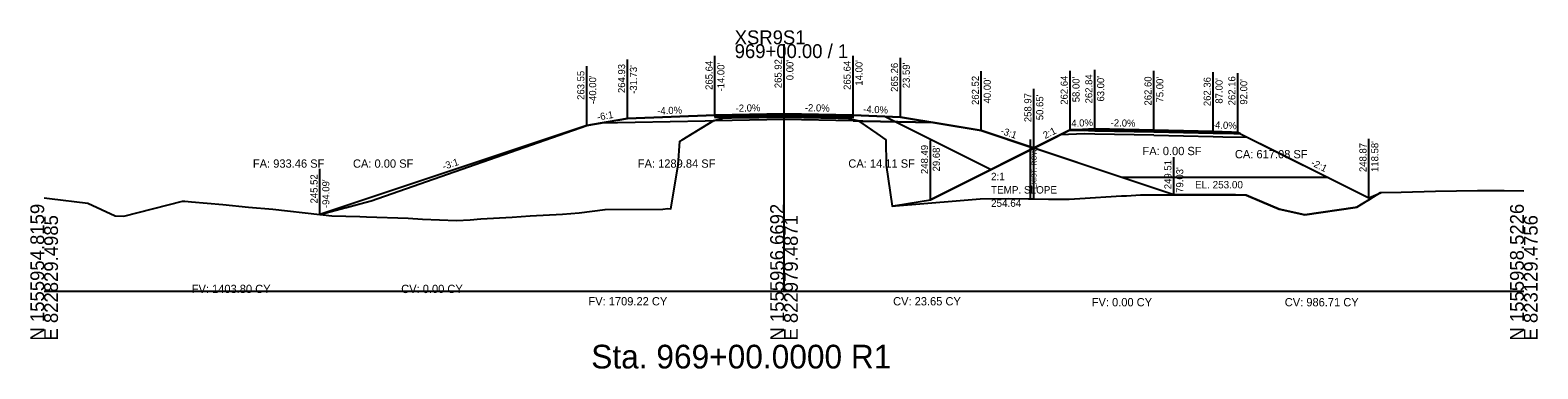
# Model space of a CAD drawing. Extents: x -26 to 823017, y -16 to 1558356.
# Drawn here: x 997.2 to 1302.8, y 9484.3 to 9552.8 of the extents above; entities that cross this region are included whole.
import ezdxf

# ---------------------------------------------------------------- set-up
doc = ezdxf.new("R2010")
doc.units = 0
for name, color, linetype in [('1', 7, 'Continuous'), ('ASPHALT_19MM1', 7, 'Continuous'), ('ASPHALT_9_5MM1', 7, 'Continuous'), ('CONST_DCH', 7, 'Continuous'), ('CONST_LV3', 7, 'Continuous'), ('Draft_XS_Grid', 7, 'Continuous'), ('Draft_XS_Text', 7, 'Continuous'), ('DTM_CORRIDOR', 7, 'Continuous'), ('DTM_P_FINISHED_GRADE2', 7, 'Continuous'), ('DTM_X_GROUND', 7, 'Continuous'), ('SLOPE_STAKES_FILL', 7, 'Continuous'), ('X_PROFILES_1', 7, 'Continuous'), ('X_TRANS_EOP', 7, 'Continuous'), ('XS_CELL', 7, 'Continuous'), ('XS_M_SHAPES_EARTHWORK', 7, 'Continuous'), ('XS_P_DR_GRAVEL', 7, 'Continuous'), ('XS_P_GROUND', 7, 'Continuous'), ('XS_P_NULL_POINT', 7, 'Continuous'), ('XS_P_SHOULDER', 7, 'Continuous'), ('XS_P_SUBGRADE_GRANULAR', 7, 'Continuous'), ('XS_P_SUBGRADE_UNDERCUT', 7, 'Continuous'), ('XS_P_TX_CLEARZONE', 7, 'Continuous'), ('XS_P_TX_FS_BS', 7, 'Continuous'), ('XS_SHEET_EW_TX_AREA', 7, 'Continuous'), ('XS_SHEET_EW_TX_VOLUME', 7, 'Continuous'), ('XS_X_ROW', 7, 'Continuous')]:
    doc.layers.add(name, color=color, linetype=linetype)

msp = doc.modelspace()

# ---------------------------------------------------------------- linework, layer by layer
at = {"layer": '1'}
msp.add_lwpolyline([(1136, 9535.35), (1136, 9535.35), (1150, 9535.63), (1164, 9535.35), (1164, 9535.35), (1164, 9535.51), (1164, 9535.51), (1150, 9535.79), (1136, 9535.51), (1136, 9535.51), (1136, 9535.35)], dxfattribs=at)
at = {"layer": 'ASPHALT_19MM1'}
for points in [[(1136, 9535.14), (1136, 9535.14), (1150, 9535.42), (1164, 9535.14), (1164, 9535.14), (1164, 9535.35), (1164, 9535.35), (1150, 9535.63), (1136, 9535.35), (1136, 9535.35), (1136, 9535.14)], [(1213, 9532.47), (1225, 9532.23), (1237, 9531.99), (1237, 9532.2), (1225, 9532.44), (1213, 9532.68), (1213, 9532.47)]]:
    msp.add_lwpolyline(points, dxfattribs=at)
at = {"layer": 'ASPHALT_9_5MM1'}
msp.add_lwpolyline([(1136, 9535.51), (1136, 9535.51), (1150, 9535.79), (1164, 9535.51), (1164, 9535.51), (1164, 9535.64), (1164, 9535.64), (1150, 9535.92), (1136, 9535.64), (1136, 9535.64), (1136, 9535.51)], dxfattribs=at)
at = {"layer": 'CONST_LV3'}
for points in [[(1150, 9535.92), (1164, 9535.64)], [(1173.59, 9535.26), (1164, 9535.64), (1164, 9535.64)], [(1110, 9533.55), (1112.74, 9534.01), (1112.74, 9534.01)], [(1179.68, 9518.49), (1203.22, 9530.25), (1208, 9532.64), (1209.25, 9532.69), (1213, 9532.84)], [(1190, 9532.52), (1180.23, 9534.15), (1180.23, 9534.15)], [(1200.65, 9528.97), (1200.97, 9529.13), (1203.1, 9530.19), (1203.22, 9530.25), (1208, 9532.64), (1209.25, 9532.69), (1213, 9532.84), (1222.01, 9532.66), (1225, 9532.6), (1234.01, 9532.14), (1237, 9531.99), (1238.25, 9532.03), (1242, 9532.16), (1260.49, 9522.92), (1260.59, 9522.87), (1261.82, 9522.26), (1268.58, 9518.87), (1270.91, 9519.91), (1271.04, 9519.97), (1275.11, 9520.08), (1282.11, 9520.26), (1290.63, 9520.39), (1296.03, 9520.36), (1300, 9520.33)], [(1242, 9532.16), (1268.82, 9518.75)], [(1000, 9518.93), (1001.08, 9518.77), (1008.83, 9517.79), (1014.39, 9515.25), (1016.12, 9515.22), (1028.04, 9518.24), (1028.49, 9518.2), (1029.87, 9518.06), (1036.24, 9517.55), (1041.42, 9517.01), (1046.39, 9516.58), (1055.89, 9515.53), (1055.91, 9515.52), (1055.91, 9515.52), (1055.91, 9515.52)]]:
    msp.add_lwpolyline(points, dxfattribs=at)
at = {"layer": 'DTM_P_FINISHED_GRADE2'}
msp.add_lwpolyline([(1055.91, 9515.52), (1066.32, 9518.3), (1110, 9533.55), (1118.27, 9534.93), (1136, 9535.64), (1150, 9535.92), (1164, 9535.64), (1173.59, 9535.26), (1190, 9532.52), (1200.65, 9528.97)], dxfattribs=at)
at = {"layer": 'DTM_X_GROUND'}
for points in [[(1000, 9518.93), (1001.08, 9518.77), (1008.83, 9517.79), (1014.39, 9515.25), (1016.12, 9515.22), (1028.04, 9518.24), (1028.49, 9518.2), (1029.87, 9518.06), (1036.24, 9517.55), (1041.42, 9517.01), (1046.39, 9516.58), (1055.89, 9515.53), (1055.91, 9515.52), (1055.91, 9515.52), (1055.91, 9515.52), (1056.64, 9515.72), (1059.4, 9516.46), (1061.27, 9516.96), (1065.77, 9518.16), (1066.32, 9518.3), (1110, 9533.55), (1110, 9533.55), (1118.27, 9534.93), (1118.27, 9534.93), (1136, 9535.64), (1136, 9535.64), (1136, 9535.64), (1150, 9535.92), (1164, 9535.64), (1164, 9535.64), (1164, 9535.64), (1173.59, 9535.26), (1173.59, 9535.26), (1190, 9532.52), (1190, 9532.52), (1190, 9532.52), (1190, 9532.52), (1190, 9532.52), (1190, 9532.52), (1190, 9532.52), (1190, 9532.52), (1190, 9532.52), (1200.65, 9528.97), (1200.97, 9529.13), (1203.1, 9530.19), (1203.22, 9530.25), (1208, 9532.64), (1209.25, 9532.69), (1213, 9532.84), (1222.01, 9532.66), (1225, 9532.6), (1234.01, 9532.14), (1237, 9531.99), (1238.25, 9532.03), (1242, 9532.16), (1260.49, 9522.92), (1260.59, 9522.87), (1261.82, 9522.26), (1268.58, 9518.87), (1270.91, 9519.91), (1271.04, 9519.97), (1275.11, 9520.08), (1282.11, 9520.26), (1290.63, 9520.39), (1296.03, 9520.36), (1300, 9520.33)], [(1000, 9518.93), (1001.08, 9518.77), (1008.83, 9517.79), (1014.39, 9515.25), (1016.12, 9515.22), (1028.04, 9518.24), (1028.49, 9518.2), (1029.87, 9518.06), (1036.24, 9517.55), (1041.42, 9517.01), (1046.39, 9516.58), (1055.89, 9515.53), (1056.55, 9515.46), (1058.3, 9515.25), (1064.02, 9515.11), (1065.32, 9515.03), (1073.77, 9514.76), (1076.71, 9514.58), (1083.59, 9514.32), (1086.36, 9514.46), (1088.56, 9514.65), (1094.86, 9514.97), (1098.53, 9515.28), (1105.11, 9515.6), (1108.5, 9515.89), (1113.71, 9516.57), (1125.46, 9516.63), (1126.47, 9516.73), (1127.04, 9516.64), (1128.57, 9525.5), (1128.87, 9530.4), (1129.32, 9530.67), (1135.77, 9534.53), (1137.42, 9534.99), (1137.72, 9535.08), (1139.37, 9535.1), (1150.53, 9535.25), (1160.99, 9535.02), (1163.1, 9534.97), (1164.97, 9534.53), (1165.12, 9534.49), (1168.81, 9531.93), (1170.63, 9530.66), (1170.68, 9525.51), (1171.94, 9517.22), (1172.16, 9517.27), (1172.59, 9517.28), (1184.92, 9518.3), (1189.79, 9518.71), (1195.54, 9518.79), (1203.63, 9518.6), (1207.8, 9518.65), (1209.96, 9518.78), (1218.42, 9519.29), (1219.47, 9519.31), (1222.25, 9519.52), (1232.85, 9519.5), (1241.51, 9519.48), (1243.7, 9519.41), (1246.91, 9518.12), (1250.36, 9516.6), (1255.59, 9515.47), (1255.61, 9515.46), (1265.77, 9516.93), (1266.13, 9517), (1267.04, 9517.53), (1270.91, 9519.97), (1275.11, 9520.08), (1282.11, 9520.26), (1290.63, 9520.39), (1296.03, 9520.36), (1300, 9520.33)], [(1000, 9518.93), (1001.08, 9518.77), (1008.83, 9517.79), (1014.39, 9515.25), (1016.12, 9515.22), (1028.04, 9518.24), (1028.49, 9518.2), (1029.87, 9518.06), (1036.24, 9517.55), (1041.42, 9517.01), (1046.39, 9516.58), (1055.89, 9515.53), (1056.55, 9515.46), (1058.3, 9515.25), (1064.02, 9515.11), (1065.32, 9515.03), (1073.77, 9514.76), (1076.71, 9514.58), (1083.59, 9514.32), (1086.36, 9514.46), (1088.56, 9514.65), (1094.86, 9514.97), (1098.53, 9515.28), (1105.11, 9515.6), (1108.5, 9515.89), (1113.71, 9516.57), (1125.46, 9516.63), (1126.47, 9516.73), (1127.04, 9516.64), (1128.57, 9525.5), (1128.87, 9530.4), (1129.32, 9530.67), (1135.77, 9534.53), (1137.42, 9534.99), (1137.72, 9535.08), (1139.37, 9535.1), (1150.53, 9535.25), (1160.99, 9535.02), (1163.1, 9534.97), (1164.97, 9534.53), (1165.12, 9534.49), (1168.81, 9531.93), (1170.63, 9530.66), (1170.68, 9525.51), (1171.94, 9517.22), (1172.16, 9517.27), (1172.29, 9517.27), (1172.59, 9517.32), (1179.68, 9518.49), (1191.8, 9524.54), (1194.96, 9526.13), (1195.04, 9526.16), (1195.64, 9526.46), (1199.91, 9528.6), (1200.97, 9529.13), (1203.1, 9530.19), (1203.22, 9530.25), (1208, 9532.64), (1209.25, 9532.69), (1213, 9532.84), (1222.01, 9532.66), (1225, 9532.6), (1234.01, 9532.14), (1237, 9531.99), (1238.25, 9532.03), (1242, 9532.16), (1260.49, 9522.92), (1260.59, 9522.87), (1261.82, 9522.26), (1268.58, 9518.87), (1270.91, 9519.91), (1271.04, 9519.97), (1275.11, 9520.08), (1282.11, 9520.26), (1290.63, 9520.39), (1296.03, 9520.36), (1300, 9520.33)]]:
    msp.add_lwpolyline(points, dxfattribs=at)
at = {"layer": 'X_TRANS_EOP'}
msp.add_lwpolyline([(1213, 9532.68), (1225, 9532.44), (1237, 9532.2), (1237, 9532.36), (1225, 9532.6), (1213, 9532.84), (1213, 9532.68)], dxfattribs=at)
at = {"layer": 'XS_CELL'}
for p, q in [((1150, 9500), (1150, 9550)), ((1000, 9500), (1150, 9500)), ((1150, 9500), (1300, 9500))]:
    msp.add_line(p, q, dxfattribs=at)
at = {"layer": 'XS_M_SHAPES_EARTHWORK'}
for points in [[(1055.91, 9515.52), (1056.55, 9515.46), (1058.3, 9515.25), (1064.02, 9515.11), (1065.32, 9515.03), (1073.77, 9514.76), (1076.71, 9514.58), (1083.59, 9514.32), (1086.36, 9514.46), (1088.56, 9514.65), (1094.86, 9514.97), (1098.53, 9515.28), (1105.11, 9515.6), (1108.5, 9515.89), (1113.71, 9516.57), (1125.46, 9516.63), (1126.47, 9516.73), (1127.04, 9516.64), (1128.57, 9525.5), (1128.87, 9530.4), (1129.32, 9530.67), (1135.66, 9534.47), (1134, 9534.43), (1112.74, 9534.01), (1110, 9533.55)], [(1135.66, 9534.47), (1135.77, 9534.53), (1137.42, 9534.99), (1137.72, 9535.08), (1139.37, 9535.1), (1150.53, 9535.25), (1160.99, 9535.02), (1163.1, 9534.97), (1164.97, 9534.53), (1165.12, 9534.49), (1165.18, 9534.45), (1164, 9534.47), (1150, 9534.75), (1136, 9534.47)], [(1165.18, 9534.45), (1168.81, 9531.93), (1170.63, 9530.66), (1170.68, 9525.51), (1171.94, 9517.22), (1172.16, 9517.27), (1172.59, 9517.28), (1184.92, 9518.3), (1189.79, 9518.71), (1195.54, 9518.79), (1200.65, 9518.67), (1200.65, 9528.97), (1190, 9532.52), (1180.23, 9534.15), (1166, 9534.43)]]:
    msp.add_lwpolyline(points, close=True, dxfattribs=at)
at = {"layer": 'XS_P_DR_GRAVEL'}
for points in [[(1209.25, 9532.69), (1208, 9532.64), (1207.89, 9532.59), (1207.86, 9532.57), (1211.72, 9532.5), (1213, 9532.47), (1213, 9532.56), (1213, 9532.84), (1209.25, 9532.69)], [(1240.75, 9532.21), (1237, 9532.36), (1237, 9532.08), (1237, 9531.99), (1241.18, 9531.91), (1242.57, 9531.88), (1242.43, 9531.95), (1242, 9532.16), (1240.75, 9532.21)]]:
    msp.add_lwpolyline(points, dxfattribs=at)
at = {"layer": 'XS_P_GROUND'}
msp.add_line((1170.51, 9535.38), (1191.99, 9524.64), dxfattribs=at)
for points in [[(1118.27, 9534.93), (1110, 9533.55), (1055.91, 9515.52)], [(1173.59, 9535.26), (1190, 9532.52), (1200.65, 9528.97)], [(1229.03, 9519.51), (1190, 9532.52), (1190, 9532.52), (1173.59, 9535.26), (1173.59, 9535.26)], [(1208, 9532.64), (1179.68, 9518.49)], [(1242, 9532.16), (1268.58, 9518.87)], [(1268.82, 9518.65), (1268.82, 9518.65), (1267.04, 9517.53), (1267.04, 9517.53), (1266.13, 9517), (1265.77, 9516.93), (1265.77, 9516.93), (1265.77, 9516.93), (1255.61, 9515.46), (1255.61, 9515.46), (1255.61, 9515.46), (1255.59, 9515.47), (1255.59, 9515.47), (1250.36, 9516.6), (1250.36, 9516.6), (1246.91, 9518.12), (1246.91, 9518.12), (1243.7, 9519.41), (1243.7, 9519.41), (1243.7, 9519.41), (1241.51, 9519.48), (1241.51, 9519.48), (1232.85, 9519.5), (1232.85, 9519.5), (1229.03, 9519.51)], [(1268.82, 9518.65), (1268.82, 9518.65), (1267.04, 9517.53), (1267.04, 9517.53), (1266.13, 9517), (1265.77, 9516.93), (1265.77, 9516.93), (1265.77, 9516.93), (1255.61, 9515.46), (1255.61, 9515.46), (1255.61, 9515.46), (1255.59, 9515.47), (1255.59, 9515.47), (1250.36, 9516.6), (1250.36, 9516.6), (1246.91, 9518.12), (1246.91, 9518.12), (1243.7, 9519.41), (1243.7, 9519.41), (1243.7, 9519.41), (1241.51, 9519.48), (1241.51, 9519.48), (1232.85, 9519.5), (1232.85, 9519.5), (1229.03, 9519.51)]]:
    msp.add_lwpolyline(points, dxfattribs=at)
at = {"layer": 'XS_P_SHOULDER'}
for points in [[(1136, 9535.64), (1118.27, 9534.93)], [(1164, 9535.64), (1173.59, 9535.26)], [(1208, 9532.64), (1209.25, 9532.69), (1213, 9532.84)], [(1242, 9532.16), (1240.75, 9532.21), (1237, 9532.36)]]:
    msp.add_lwpolyline(points, dxfattribs=at)
at = {"layer": 'XS_P_SUBGRADE_GRANULAR'}
for points in [[(1136, 9534.47), (1134, 9534.43), (1112.74, 9534.01)], [(1150, 9534.75), (1136, 9534.47)], [(1164, 9534.47), (1164, 9534.47), (1150, 9534.75)], [(1164, 9534.47), (1166, 9534.43), (1180.23, 9534.15)], [(1213, 9531.8), (1211, 9531.84), (1206, 9531.64)], [(1225, 9531.56), (1213, 9531.8)], [(1225, 9531.56), (1237, 9531.32)], [(1237, 9531.32), (1239, 9531.28), (1243.96, 9531.18)]]:
    msp.add_lwpolyline(points, dxfattribs=at)
at = {"layer": 'XS_P_SUBGRADE_UNDERCUT'}
msp.add_lwpolyline([(1218.52, 9523.01), (1200.65, 9528.97), (1208, 9532.64), (1212.78, 9532.85), (1224.87, 9532.61), (1236.96, 9532.37), (1242, 9532.16), (1250.71, 9527.84), (1260.3, 9523.01)], close=True, dxfattribs=at)
at = {"layer": 'XS_P_TX_CLEARZONE'}
for p, q in [((1118.27, 9534.93), (1118.27, 9546.93)), ((1136, 9535.64), (1136, 9547.64)), ((1150, 9535.92), (1150, 9547.92)), ((1164, 9535.64), (1164, 9547.64)), ((1173.59, 9535.26), (1173.59, 9547.26)), ((1110, 9533.55), (1110, 9545.55)), ((1190, 9532.52), (1190, 9544.52)), ((1190, 9532.52), (1190, 9544.52)), ((1208, 9532.64), (1208, 9544.64)), ((1213, 9532.84), (1213, 9544.84)), ((1225, 9532.6), (1225, 9544.6)), ((1237, 9532.36), (1237, 9544.36)), ((1242, 9532.16), (1242, 9544.16)), ((1200.65, 9528.97), (1200.65, 9540.97)), ((1179.68, 9518.49), (1179.68, 9530.49)), ((1268.58, 9518.87), (1268.58, 9530.87)), ((1229.03, 9519.51), (1229.03, 9527.14)), ((1055.91, 9515.52), (1055.91, 9524.77))]:
    msp.add_line(p, q, dxfattribs=at)
at = {"layer": 'XS_X_ROW'}
msp.add_line((1200, 9518.69), (1200, 9530.69), dxfattribs=at)

# ---------------------------------------------------------------- texts
at = {"layer": 'CONST_DCH'}
for p in [(1135.92, 9535.52), (1149.92, 9535.8), (1163.92, 9535.52)]:
    msp.add_text('X', height=0.24, dxfattribs=at).set_placement(p)
at = {"layer": 'CONST_LV3'}
for p in [(1173.51, 9535.14), (1189.92, 9532.4), (1200.57, 9528.85), (1228.96, 9519.39), (1268.74, 9518.63), (1055.83, 9515.4)]:
    msp.add_text('X', height=0.24, dxfattribs=at).set_placement(p)
at = {"layer": 'Draft_XS_Grid'}
msp.add_text('-', height=0.0001, dxfattribs=at).set_placement((1000, 9500))
at = {"layer": 'Draft_XS_Text'}
msp.add_text('Sta. 969+00.0000 R1', height=4.8, dxfattribs=at).set_placement((1110.92, 9484.35))
at = {"layer": 'DTM_CORRIDOR'}
for p in [(1212.92, 9532.72), (1224.92, 9532.48), (1236.92, 9532.24)]:
    msp.add_text('X', height=0.24, dxfattribs=at).set_placement(p)
at = {"layer": 'SLOPE_STAKES_FILL'}
for p in [(1268.5, 9518.75), (1179.6, 9518.37)]:
    msp.add_text('X', height=0.24, dxfattribs=at).set_placement(p)
at = {"layer": 'X_PROFILES_1'}
msp.add_text('X', height=0.24, dxfattribs=at).set_placement((1268.74, 9518.63))
at = {"layer": 'XS_CELL'}
for s, p in [('XSR9S1', (1140, 9550)), ('969+00.00 / 1', (1140, 9547.2))]:
    msp.add_text(s, height=2.8, dxfattribs=at).set_placement(p)
for s, p in [('N 1555954.8159', (1000, 9490)), ('N 1555956.6692', (1150, 9490)), ('N 1555958.5226', (1300, 9490)), ('E 822829.4985', (1002.8, 9490)), ('E 822979.4871', (1152.8, 9490)), ('E 823129.4756', (1302.8, 9490))]:
    msp.add_text(s, height=2.8, rotation=90, dxfattribs=at).set_placement(p)
at = {"layer": 'XS_P_GROUND'}
for s, p in [('2:1', (1191.97, 9522.47)), ('TEMP. SLOPE', (1191.97, 9519.77)), ('254.64', (1191.97, 9517.07))]:
    msp.add_text(s, height=1.5, dxfattribs=at).set_placement(p)
at = {"layer": 'XS_P_NULL_POINT'}
for p in [(1200.57, 9528.85), (1268.5, 9518.75), (1179.6, 9518.37), (1055.83, 9515.4)]:
    msp.add_text('X', height=0.24, dxfattribs=at).set_placement(p)
at = {"layer": 'XS_P_SHOULDER'}
for p in [(1118.2, 9534.81), (1173.51, 9535.14), (1207.92, 9532.52), (1241.92, 9532.04)]:
    msp.add_text('X', height=0.24, dxfattribs=at).set_placement(p)
at = {"layer": 'XS_P_SUBGRADE_GRANULAR'}
for p in [(1109.92, 9533.43), (1189.92, 9532.4)]:
    msp.add_text('X', height=0.24, dxfattribs=at).set_placement(p)
at = {"layer": 'XS_P_SUBGRADE_UNDERCUT'}
msp.add_text('EL. 253.00', height=1.5, dxfattribs=at).set_placement((1233.34, 9520.81))
at = {"layer": 'XS_P_TX_CLEARZONE'}
for s, p in [('265.64', (1135.52, 9540.75)), ('265.92', (1149.52, 9541.1)), ("0.00'", (1151.92, 9542.71)), ('265.64', (1163.52, 9540.75)), ("14.00'", (1165.92, 9541.61)), ('263.55', (1109.52, 9538.73)), ("-40.00'", (1111.92, 9537.87)), ('264.93', (1117.79, 9540.11)), ("-31.73'", (1120.19, 9539.95)), ("-14.00'", (1137.92, 9540.43)), ('265.26', (1173.11, 9540.35)), ("23.59'", (1175.51, 9541.09)), ('262.52', (1189.52, 9537.7)), ('262.64', (1207.52, 9537.75)), ('262.84', (1212.52, 9538.02)), ("63.00'", (1214.92, 9538.39)), ('262.60', (1224.52, 9537.59)), ('262.16', (1241.52, 9537.63)), ("40.00'", (1191.92, 9538.02)), ("58.00'", (1209.92, 9538.25)), ("75.00'", (1226.92, 9538.21)), ('262.36', (1236.52, 9537.46)), ("87.00'", (1238.92, 9537.97)), ("92.00'", (1243.92, 9537.77)), ('258.97', (1200.17, 9534.22)), ("50.65'", (1202.57, 9534.62)), ('248.49', (1179.2, 9523.72)), ("29.68'", (1181.6, 9524.25)), ('248.87', (1268.1, 9524.12)), ("118.58'", (1270.5, 9524.14)), ('249.51', (1228.55, 9520.65)), ('245.52', (1055.43, 9517.77)), ("-94.09'", (1057.83, 9516.82)), ("79.03'", (1230.95, 9519.91))]:
    msp.add_text(s, height=1.44, rotation=90, dxfattribs=at).set_placement(p)
at = {"layer": 'XS_P_TX_FS_BS'}
for s, rotation, p in [('-4.0%', 2.2906, (1124.32, 9535.77)), ('-2.0%', 1.1458, (1140.2, 9536.32)), ('-2.0%', 358.8542, (1154.22, 9536.44)), ('-4.0%', 357.7094, (1166.03, 9536.16)), ('-6:1', 9.4642, (1112.22, 9534.53)), ('4.0%', 2.2906, (1208.27, 9533.26)), ('-2.0%', 358.8542, (1216.22, 9533.38)), ('-4.0%', 357.7094, (1236.73, 9532.98)), ('-3:1', 341.5641, (1193.79, 9531.89)), ('2:1', 26.5651, (1202.96, 9530.8)), ('-3:1', 18.4332, (1081.04, 9524.53)), ('-2:1', 333.4349, (1256.7, 9525.54))]:
    msp.add_text(s, height=1.44, rotation=rotation, dxfattribs=at).set_placement(p)
at = {"layer": 'XS_SHEET_EW_TX_AREA'}
for s, p in [('FA: 0.00 SF', (1222.68, 9527.54)), ('CA: 617.08 SF', (1241.42, 9526.9)), ('FA: 933.46 SF', (1042.32, 9525)), ('CA: 0.00 SF', (1062.61, 9525)), ('FA: 1289.84 SF', (1120.36, 9525)), ('CA: 14.11 SF', (1163.05, 9525))]:
    msp.add_text(s, height=1.68, dxfattribs=at).set_placement(p)
at = {"layer": 'XS_SHEET_EW_TX_VOLUME'}
for s, p in [('FV: 1403.80 CY', (1029.92, 9499.62)), ('CV: 0.00 CY', (1072.39, 9499.62)), ('FV: 1709.22 CY', (1110.35, 9497.12)), ('CV: 23.65 CY', (1172.12, 9497.12)), ('FV: 0.00 CY', (1212.39, 9496.93)), ('CV: 986.71 CY', (1251.53, 9496.93))]:
    msp.add_text(s, height=1.68, dxfattribs=at).set_placement(p)
at = {"layer": 'XS_X_ROW'}
msp.add_text('EXIST. ROW', height=1, rotation=90, dxfattribs=at).set_placement((1201.2, 9520.69))

doc.saveas('drawing.dxf')
